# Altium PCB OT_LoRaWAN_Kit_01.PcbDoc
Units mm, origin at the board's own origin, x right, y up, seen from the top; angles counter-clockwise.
Board outline 53.4 x 48.3 mm, 2 copper layers (Top Layer, Bottom Layer); 35 components, 39 nets, 128 pads, 78 vias.
Unrouted connection lines stored in the file: 22.
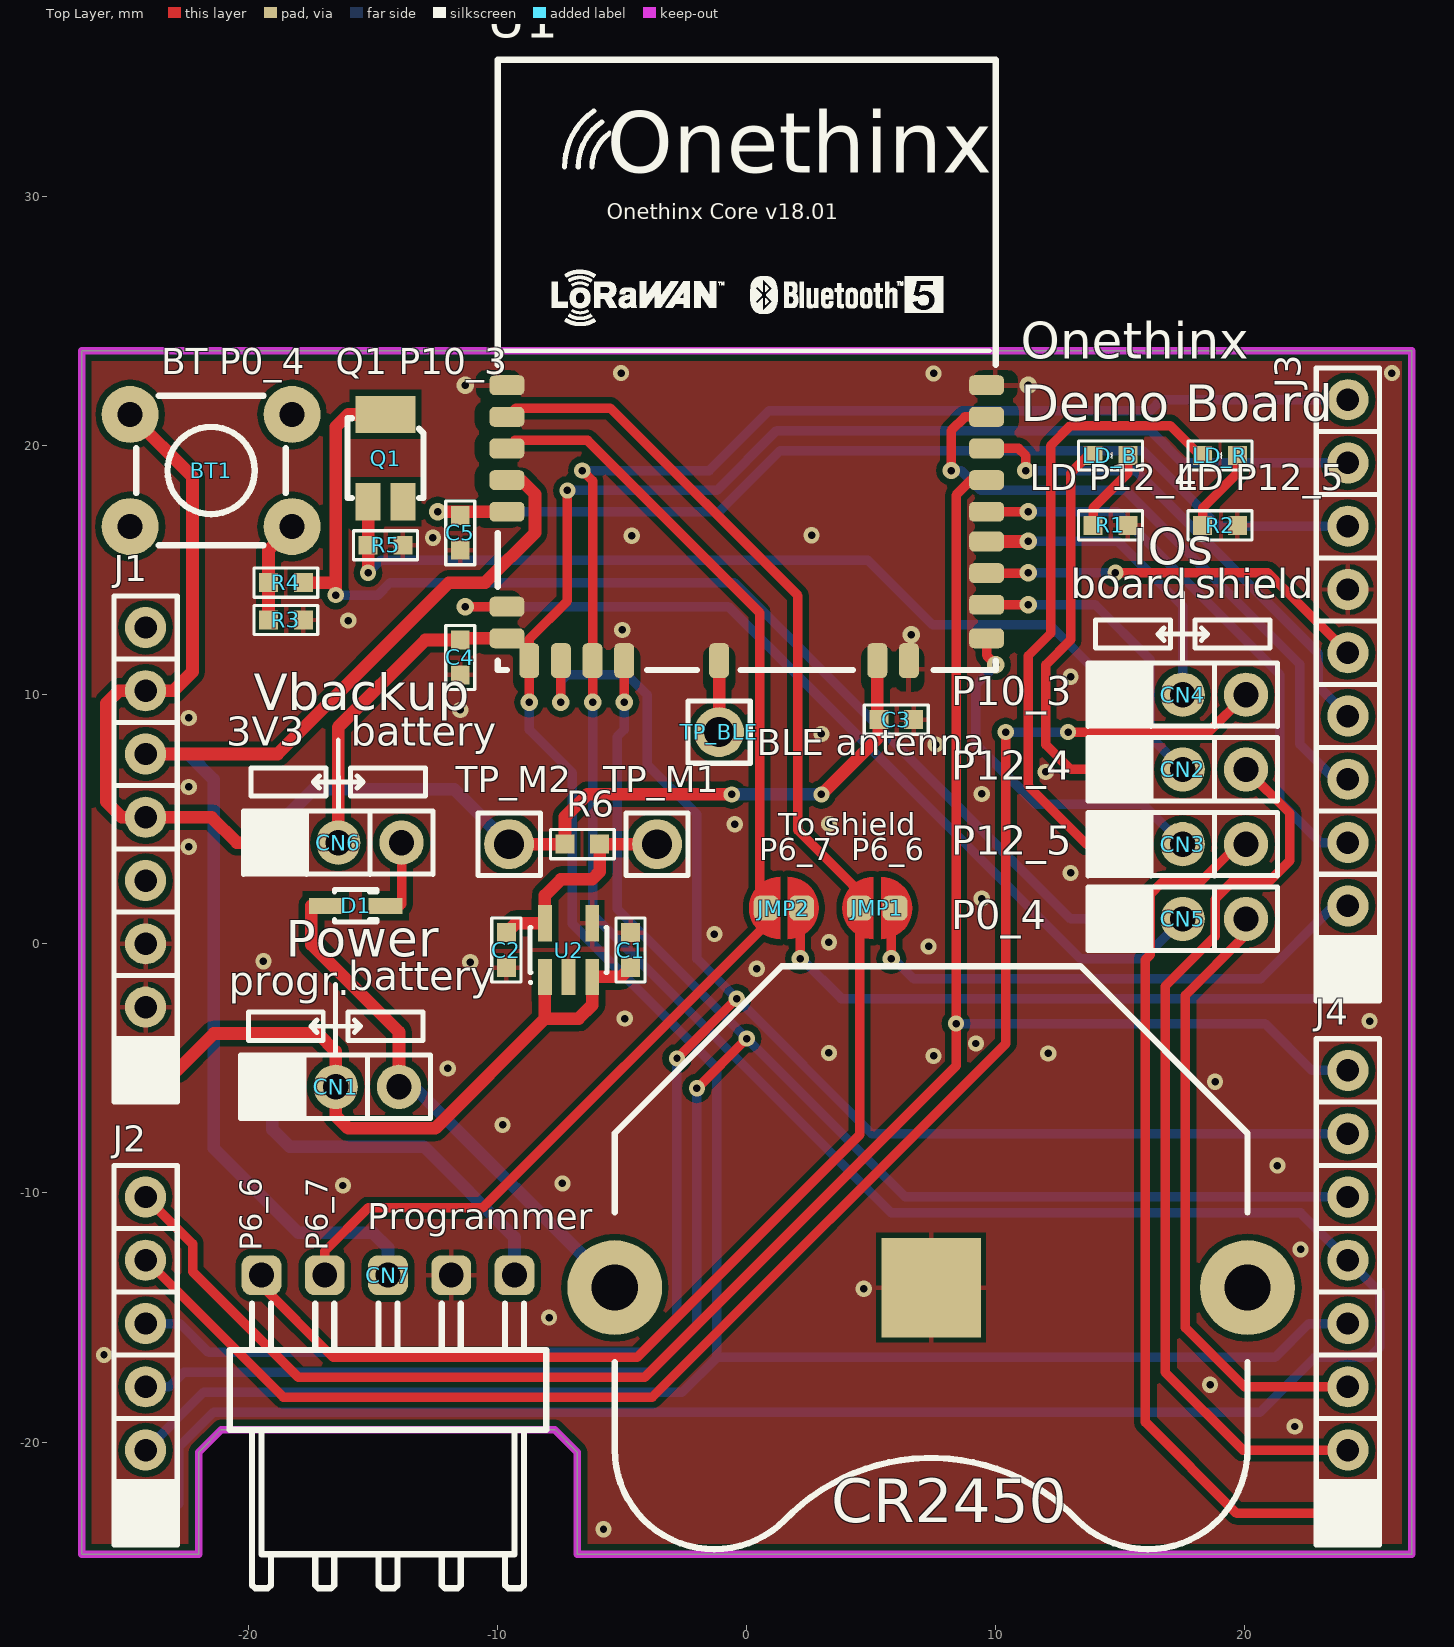
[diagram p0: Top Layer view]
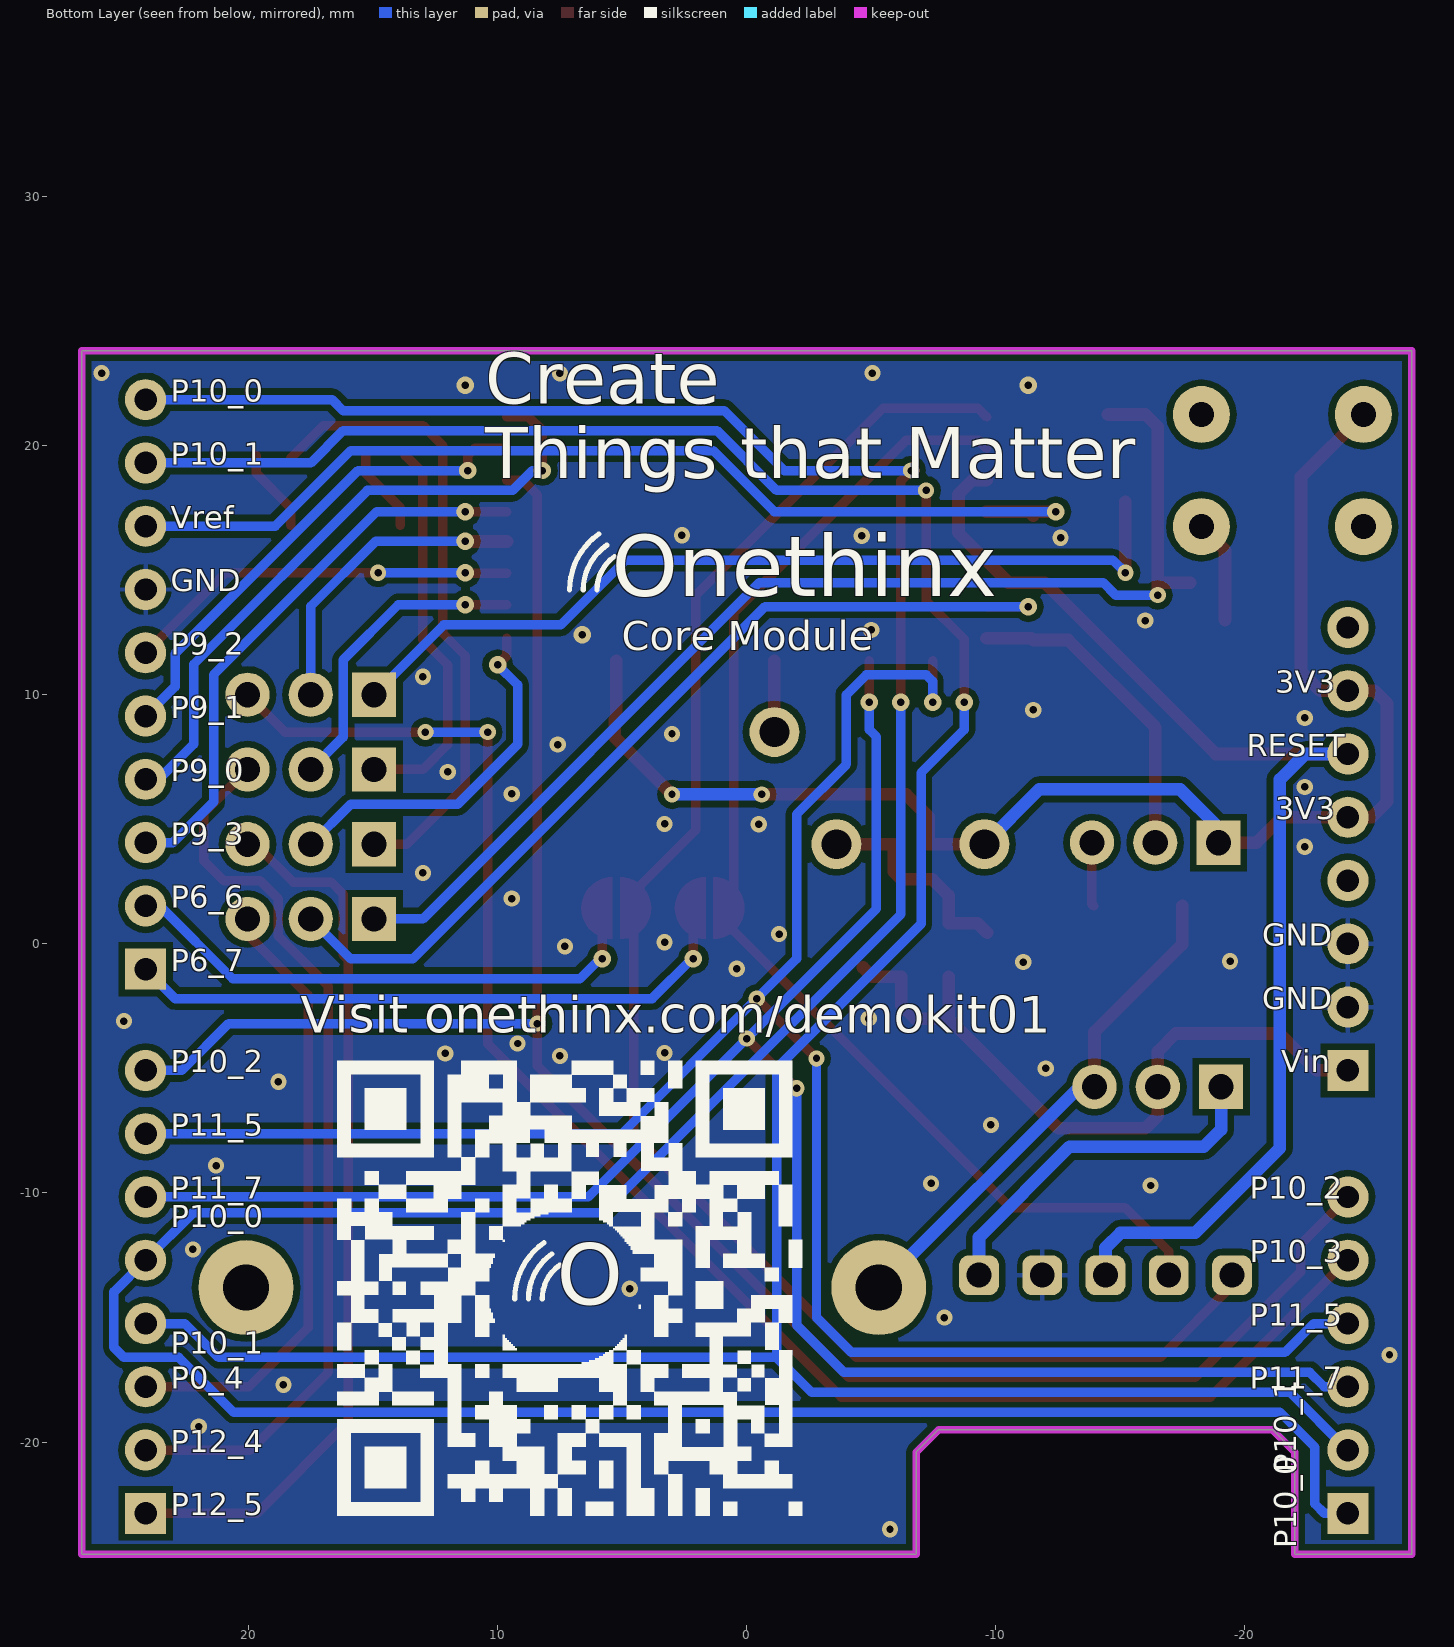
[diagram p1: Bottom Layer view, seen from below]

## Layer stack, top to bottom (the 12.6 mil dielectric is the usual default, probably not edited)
Top Solder: solder mask 0.0102, Solder Resist, Dk 3.5
Top Layer: signal copper 0.0356
Dielectric 1: dielectric 0.32, FR-4, Dk 4.8
Bottom Layer: signal copper 0.0356
Bottom Solder: solder mask 0.0102, Solder Resist, Dk 3.5

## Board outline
-26.7,-24.5 -26.7,23.8 26.7,23.8 26.7,-24.5 -6.8,-24.5 -6.8,-20.4 -7.7,-19.5 -21.1,-19.5 -22,-20.4 -22,-24.5

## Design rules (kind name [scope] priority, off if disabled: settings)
BoardOutlineClearance [All] p1 off: gap=0.25 ignorepadtopadclearanceinfootprint=FALSE except(0: Arc-SplitContinuation Track-SplitContinuation SMDPad-SplitContinuation THPad-SplitContinuation Via-SplitContinuation Fill-SplitContinuation Poly-SplitContinuation Region-SplitContinuation Text-SplitContinuation)
Clearance [IsRegion] p1: gap=0.254 ignorepadtopadclearanceinfootprint=FALSE except(0: Arc-Hole Track-Hole SMDPad-Hole THPad-Hole Via-Hole Fill-Hole Poly-Hole Region-Hole Text-Hole)
Clearance Clearance-xPP-xTP-xTT [All] p2: gap=0.15 ignorepadtopadclearanceinfootprint=FALSE except(0: Arc-Hole Track-Hole SMDPad-Hole THPad-Hole Via-Hole Fill-Hole Poly-Hole Region-Hole Text-Hole)
ComponentClearance [All] p1 off: gap=0.25 collisioncheckmode=3 verticalgap=0.25 showdistances=FALSE
DiffPairsRouting [All] p1: maxlimit=0.25 minlimit=0.25 mostfreqgap=0.25 toplayer_minwidth=0.381 toplayer_maxwidth=0.381 toplayer_prefwidth=0.381 bottomlayer_minwidth=0.381 bottomlayer_maxwidth=0.381 bottomlayer_prefwidth=0.381 maxuncoupledlength=12.5
Height [All] p1: minheight=0 maxheight=25 prefheight=12.5
HoleSize HoleSize-PTH [All] p1: absolutevalues=TRUE maxlimit=2 minlimit=0.25 maxpercent=80.000 minpercent=20.000
HoleToHoleClearance [All] p1: gap=0.35 allowstackedmicrovias=TRUE
MinimumAnnularRing "Minimum IAR  >0.45mm" [((ObjectKind = 'Pad') OR (ObjectKind = 'Via')) And (Layer = 'MultiLayer') And (HoleDiameter > AsMM(0.45))] p1: minimumring=0.175 // minimum inner annular ring for pads > 0.45mm finished hole size
MinimumAnnularRing "Minimum IAR <=0.45mm" [((ObjectKind = 'Pad') OR (ObjectKind = 'Via')) And (Layer = 'MultiLayer') And (HoleDiameter <= AsMM(0.45))] p2: minimumring=0.175 // minimum inner annular ring for pads <= 0.45mm finished hole size
MinimumSolderMaskSliver [All] p1: minsoldermaskwidth=0.08
PlaneClearance PlaneClearance-IPI [All] p1: clearance=0.25
PlaneConnect [All] p1: planeconnectstyle=Relief reliefexpansion=0.175 reliefentries=4 reliefconductorwidth=0.2 reliefairgap=0.2
PolygonConnect [ISVIA OR InComponent('NT1')] p1: connectstyle=Direct reliefconductorwidth=0.254 reliefentries=4 polygonreliefangle="90 Angle" airgapwidth=0.254
PolygonConnect PolygonConnect-xTW [All] p2: connectstyle=Relief reliefconductorwidth=0.2 reliefentries=4 polygonreliefangle="90 Angle" airgapwidth=0.2
RoomDefinition Cy_LoRaWAN_Kit_01 [InComponentClass('Cy_LoRaWAN_Kit_01')] p1: confinementstyle=ConfineOut formatcopy=TRUE lockcomponents=FALSE outline 39,-23 45.5,-23 45.5,-17 39,-17
RoutingCorners [All] p1: cornerstyle=45-Degree minsetback=2.5 maxsetback=2.5
RoutingVias [All] p1: holewidth=0.3 width=0.65 viastyle="Through Hole" minholewidth=0.25 minwidth=0.6 maxholewidth=0.9 maxwidth=1.25
RoutingVias "RoutingVias > 0.45mm" [(ObjectKind = 'Via') And (HoleDiameter > AsMM(0.45))] p2 off: holewidth=0.5 width=0.85 viastyle="Through Hole" minholewidth=0.5 minwidth=0.85 maxholewidth=0.9 maxwidth=1.25 // finishet hole size > 0.45mm
RoutingVias "RoutingVias <= 0.45mm" [(ObjectKind = 'Via') And (HoleDiameter <= AsMM(0.45))] p3 off: holewidth=0.3 width=0.65 viastyle="Through Hole" minholewidth=0.25 minwidth=0.6 maxholewidth=0.45 maxwidth=0.8 // finishet hole size <= 0.45mm
SilkToSilkClearance [All] p1 off: silktosilkclearance=0.2
SilkToSolderMaskClearance SilkscreenOverComponentPads [IsPad] p1 off: minsilkscreentomaskgap=0.2 clearancetoexposedcopper=TRUE
SolderMaskExpansion [All] p1: expansion=0
Width Width-xTW [All] p1: maxlimit=1.5 minlimit=0.15 preferedwidth=0.2
19 further rules are at their usual default settings.

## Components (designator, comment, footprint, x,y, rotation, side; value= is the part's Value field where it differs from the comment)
BT1 "BT P0_4" "BUTTON TACT6x6" -21.5,19 r90 top
C1 "1uF" 0603C-GENERIC -4.665,-0.25 r270 top
C2 "1uF" 0603C-GENERIC -9.652,-0.25 r90 top
C3 "100nF" 0603C-GENERIC 6,9 r180 top
C4 "100nF" 0603C-GENERIC -11.5,11.5 r90 top
C5 "100nF" 0603C-GENERIC -11.5,16.5 r90 top
CN1 "CONNECTOR 1x3" HEADER-1X3 -19.04,-5.734 r90 top
CN2 "CONNECTOR 1x3" HEADER-1X3 14.96,7.006 r90 top
CN3 "CONNECTOR 1x3" HEADER-1X3 14.96,4.006 r90 top
CN4 "CONNECTOR 1x3" HEADER-1X3 14.96,10.006 r90 top
CN5 "CONNECTOR 1x3" HEADER-1X3 14.96,1.006 r90 top
CN6 "CONNECTOR 1x3" HEADER-1X3 -18.937,4.07 r90 top
CN7 "Programmer" "CON Molex 22053051" -14.4,-13.3 r0 top
CR2450 "BAT" "BATT_2450 clip - TH" 7.4,-13.8 r180 top
D1 "BAS16HT1G" SOD323 -15.7,1.524 r0 top
J1 "CONNECTOR 1x8" "SOCKET 2.54 1X8 TH" -24.13,-5.08 r180 top
J2 "CONNECTOR 1x6" "SOCKET 2.54 1X6 TH" -24.13,-22.86 r180 top
J3 "CONNECTOR 1x10" "SOCKET 2.54 1X10 TH" 24.13,-1.016 r180 top
J4 "CONNECTOR 1x8" "SOCKET 2.54 1X8 TH" 24.13,-22.86 r180 top
JMP1 "SWD to shield" "SOLDER JUMPER" 5.24,1.433 r180 top
JMP2 "SWD to shield" "SOLDER JUMPER" 1.489,1.438 r180 top
LD_B "LD P12_4" "LED SMD 0603 (1608)" 14.6,19.6 r180 top
LD_R "LD P12_5" "LED SMD 0603 (1608)" 19,19.6 r180 top
Q1 "Q1 P10_3" PLCC-3_CEB -14.5,19.5 r90 top
R1 "10K" 0603R-GENERIC 14.6,16.8 r180 top
R2 "10K" 0603R-GENERIC 19,16.8 r180 top
R3 "1M" 0603R-GENERIC -18.5,13 r180 top
R4 "1K" 0603R-GENERIC -18.5,14.5 r0 top
R5 "47K" 0603R-GENERIC -14.5,16 r180 top
R6 "0R" 0603R-GENERIC -6.6,4 r0 top
TP_BLE "BLE antenna" "TestPoint 2mm" -1.11,8.5 r0 top
TP_M1 "TestPoint" "TestPoint 2mm" -3.6,4 r90 top
TP_M2 "TestPoint" "TestPoint 2mm" -9.537,4 r90 top
U1 "Onethinx Core V18.01" OnethinxCore_18_01 0,23.495 r0 top
U2 "TPS78330DDC" SOT-23-5 -7.152,-0.25 r0 top

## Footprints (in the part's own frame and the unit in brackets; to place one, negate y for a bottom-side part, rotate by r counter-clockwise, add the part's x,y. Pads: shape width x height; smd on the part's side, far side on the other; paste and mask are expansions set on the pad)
0603C-GENERIC [mil] "CAPACITOR 0603"
  rect 30x30 smd: 1(-27.56,0) 2(27.44,0)
  silkscreen extent -51,-23 50,23, body extent -32,-15 31,15, height 19
0603R-GENERIC [mil] "RESISTOR 0603"
  rect 30x30 smd: 1(-27.5,0) 2(27.5,0)
  silkscreen extent -50,-23 50,23, body extent -32,-15 32,15, height 19
"BATT_2450 clip - TH" [mm] "Battery CR2450 clip"
  rect 4x4 smd: MINUS(0,0)
  round 3.81 hole 1.85: PLUS(-12.7,0) PLUS(12.7,0)
  silkscreen extent -12.7,-12.9 12.7,10.5
"BUTTON TACT6x6" [mm]
  round 2.286 hole 1: 1(-2.25,3.25) 2(2.25,3.25) 3(-2.25,-3.25) 4(2.25,-3.25)
  silkscreen extent -3,-3 3,3, body extent -3,-3.85 3,3.85, height 9.5
"CON Molex 22053051" [mm] "5 way 2.54mm RA TH"
  rrect50% 1.6x1.6 hole 1: 1(-5.08,0) 2(-2.54,0) 3(0,0) 4(2.54,0) 5(5.08,0)
  silkscreen extent -6.35,-12.57 6.35,-1.14
HEADER-1X3 [mil]
  rect 70x70 hole 40: 1(-0.25,0)
  round 70 hole 40: 2(-0.25,-100) 3(-0.25,-200)
  silkscreen extent -50,-250 50,50, body extent -50,-250 50,50, height 354
"LED SMD 0603 (1608)" [mil] "LED 0603"
  rect 30x30 smd: A(27.5,0) K(-27.5,0)
  silkscreen extent -50,-23 50,23, body extent -30,-15 30,15, height 43
OnethinxCore_18_01 [mm] "Onethinx LoRaWAN Core V18.01"
  rrect50% 1.4x0.8 smd: 1(-9.625,-1.07) 2(-9.625,-2.34) 3(-9.625,-3.61) 4(-9.625,-4.88) 5(-9.625,-6.15) 6(-9.625,-9.96) 7(-9.625,-11.23) 15(9.625,-11.23) 16(9.625,-9.882) 17(9.625,-8.612) 18(9.625,-7.342) 19(9.625,-6.15) 20(9.625,-4.88) 21(9.625,-3.61) 22(9.625,-2.34) 23(9.625,-1.07)
  rrect50% 0.8x1.4 smd: 8(-8.73,-12.125) 9(-7.46,-12.125) 10(-6.19,-12.125) 11(-4.92,-12.125) 12(-1.11,-12.125) 13(5.24,-12.125) 14(6.51,-12.125)
  silkscreen extent -10,-12.5 10,12, body extent -8.5,-11 8.5,10.54, height 1.7
PLCC-3_CEB [mm]
  rect 1.5x1 smd: B(-1.75,-0.7) E(-1.75,0.7)
  rect 1.5x2.4 smd: C(1.75,0)
  silkscreen extent -1.6,-1.53 1.6,1.53, body extent -1.75,-1.4 1.75,1.4, height 1.95
"SOCKET 2.54 1X6 TH" [mil] "SOCKET 2.54 1X6 TH"
  rect 65x65 hole 35.43: 1(0,0)
  round 65 hole 35.43: 2(0,-100) 3(0,-200) 4(0,-300) 5(0,-400) 6(0,-500)
  silkscreen extent -50,-550 50,50, body extent -50,-550 50,50, height 295
"SOCKET 2.54 1X8 TH" [mil] "SOCKET 2.54 1X8 TH"
  rect 65x65 hole 35.43: 1(0,0)
  round 65 hole 35.43: 2(0,-100) 3(0,-200) 4(0,-300) 5(0,-400) 6(0,-500) 7(0,-600) 8(0,-700)
  silkscreen extent -50,-750 50,50, body extent -50,-750 50,50, height 295
"SOCKET 2.54 1X10 TH" [mil] "SOCKET 2.54 1X10 TH"
  rect 65x65 hole 35.43: 1(0,0)
  round 65 hole 35.43: 2(0,-100) 3(0,-200) 4(0,-300) 5(0,-400) 6(0,-500) 7(0,-600) 8(0,-700) 9(0,-800) 10(0,-900)
  silkscreen extent -50,-950 50,50, body extent -50,-950 50,50, height 295
SOD323 [mm]
  rect 1.35x0.65 smd: A(-1.2,0) K(1.2,0)
  silkscreen extent -0.85,-0.65 0.85,0.65, body extent -1.25,-0.63 1.25,0.63, height 0.9
"SOLDER JUMPER" [mm] "Solder Jumper 2mm"
  rrect50% 1x1 smd paste-10 mask+0: A(-0.711,0) B(0.711,0)
  Top Layer region: -0.152,1.25 -0.152,-1.25 -0.629,-1.155 -1.032,-0.885 -1.302,-0.482 -1.397,-0.005 -1.397,-0.005 -1.397,0.005 -1.302,0.482 -1.032,0.885 -0.629,1.155 -0.152,1.25
  Top Layer region: 0.152,-1.25 0.152,1.25 0.629,1.155 1.032,0.885 1.302,0.482 1.397,0.005 1.397,0.005 1.397,-0.005 1.302,-0.482 1.032,-0.885 0.629,-1.155 0.152,-1.25
SOT-23-5 [mm]
  rect 0.55x1.45 smd: 1(-0.95,-1.075) 2(0,-1.075) 3(0.95,-1.075) 4(0.95,1.075) 5(-0.95,1.075)
  silkscreen extent -1.57,-1.35 1.55,0.9, body extent -1.45,-1.4 1.45,1.4, height 1.09
"TestPoint 2mm" [mm] "Test Point 2mm"
  round 2 hole 1.2: 1(0,0)
  silkscreen extent -1.25,-1.25 1.25,1.25

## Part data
BT1: library part SW-TACT, "FSM4JH"
C1 C2 C3 C4 C5: library part CAP, "Capacitor"
CN1 CN2 CN3 CN4 CN5 CN6: "Harwin M20-9990345"
CN7: library part "CONNECTOR 1x5", "CON Molex 22053051"
CR2450: "Battery"
D1: library part Diode, "Diode"
JMP1: library part SolderJumper
JMP2: library part SolderJumper, "Solder Jumper"
LD_B: library part LED, "Wurth 150060BS73220"
LD_R: library part LED, "Wurth 150060RS75000"
Q1: library part Phototransistor, "Phototransistor Vishay VEMT4700-GS08"
R1 R2 R3 R4 R5 R6: library part RES, "Resistor"
TP_BLE: library part TestPoint, "Test Point"
TP_M1 TP_M2: "Test Point"
U1: library part Onethinx_Core_18_01, "PSoC Mixed Signal Array"
U2: library part "Voltage Regulator_EN_ADJ"

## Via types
v1: diameter 0.65, hole 0.3, Top Layer to Bottom Layer, tented both sides, 60 vias
v2: diameter 0.7, hole 0.3, Top Layer to Bottom Layer, tented both sides, 18 vias

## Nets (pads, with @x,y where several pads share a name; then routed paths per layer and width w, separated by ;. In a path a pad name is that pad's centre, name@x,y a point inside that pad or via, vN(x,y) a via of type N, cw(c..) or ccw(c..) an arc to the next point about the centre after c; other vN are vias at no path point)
3V3: BT1.2 BT1.4 C3.2 CN6.1 J1.5 J1.7 R6.1 TP_M2.1 U1.13 | length 58.6
  Top Layer w0.508: BT1.2 -22.25,18.75 -22.25,10.924 -23.014,10.16 J1.7 -25.2,10.16 -25.7,9.66 -25.7,5.7 -25.08,5.08 J1.5 -21.48,5.08 -20.464,4.064 CN6.1 ; TP_M2.1 R6.1 -7.299,5.101 -6.4,6 v1(-0.6,6) ; v1(3,6) 5.303,8.303 C3.2 5.24,9.063 U1.13
  Bottom Layer w0.508: CN6.1 -18.937,4.663 -17.4,6.2 -11.737,6.2 TP_M2.1 ; v1(-0.6,6) v1(3,6)
"BUTTON / L_POWER": CN5.1 Q1.C R4.2 | length 47.5
  Top Layer w0.508: R4.2 -16.5,14.5 ; v1(-16.5,14) -16.5,14.5 ; Q1.C -16,21.25 -16.5,20.75 -16.5,14.5
  Bottom Layer w0.381: v1(-16.5,14) -14.808,14 -14.308,14.5 -0.5,14.5 13,1 CN5.1
GND: C1.1 C2.1 C3.1 C4.1 C5.1 CN7.4 CR2450.MINUS J1.2 J1.3 J3.7 R1.1 R2.1 R3.1 R5.1 U1.1 U1.14 U1.23 U2.2 U2.4
  other v1: -5.75,-23.5 22,-19.373 18.6,-17.7 -25.8,-16.5 -7.934,-15 4.699,-13.843 22.23,-12.266 -16.21,-9.7 -7.4,-9.616 21.3,-8.9 -9.8,-7.266 18.8,-5.533 -12,-5 7.5,-4.5 12.1,-4.4 3.3,-4.378 9.2,-4 25,-3.1 -4.9,-3 0.4,-1 -11.1,-0.731 -19.4,-0.7 7.3,-0.104 3.3,0.064 -1.3,0.393 9.431,1.815 13,2.847 -22.4,3.9 -0.482,4.8 3.3,4.815 9.431,6.019 -22.4,6.3 12,6.9 7.584,8 3,8.427 -22.4,9.071 -11.5,9.39 13,10.72 -5,12.6 -16,12.976 -12.6,16.3 -4.62,16.385 2.6,16.4 7.5,22.896 -5.043,22.913 25.9,22.913
  other v2: 6.6,12.4 -11.3,22.425 11.3,22.425
LED_B: CN2.1 LD_B.A | length 15.7
  Top Layer w0.381: LD_B.A@13.701,19.6 13,18.898 13,12.2 12,11.2 12,8 13,7 CN2.1
LED_R: CN3.1 LD_R.A | length 25.6
  Top Layer w0.381: CN3.1 13.64,4 11.3,6.34 11.3,11.565 12.2,12.465 12.2,20 13,20.8 17.002,20.8 LD_R.A@18.302,19.5
LIGHT: CN4.1 Q1.E R5.2 | length 35.5
  Top Layer w0.508: v1(-15.2,14.9) -15.198,14.902 R5.2 -15.2,16.002 Q1.E
  Bottom Layer w0.381: v1(-15.2,14.9) -14.7,15.4 4.865,15.4 7.465,12.8 12.16,12.8 CN4.1
NetBT1_1: BT1.1 BT1.3 R3.2 R4.1 | length 4.1
  Top Layer w0.508: R3.2 R4.1 -19.199,15.801 BT1.3
NetC2_2: C2.2 R6.2 TP_M1.1 U2.5 | length 8.8
  Top Layer w0.508: C2.2 -9.274,0.825 U2.5 -8.102,1.945 -7.458,2.588 -6.212,2.588 -5.902,2.898 R6.2 TP_M1.1
NetCN6_3: CN6.3 D1.K | length 2.6
  Top Layer w0.381: D1.K@-13.925,1.524 -13.857,1.592 CN6.3
NetJ3_1: J3.1 JMP2.A | length 25.1
  Top Layer w0.381: v2(2.143,-0.6) 2.143,0.283 2.143,1.381 JMP2.A
  Bottom Layer w0.381: v2@2.2,-0.6 3.8,-2.2 22.946,-2.2 J3.1
NetJ3_2: J3.2 JMP1.A | length 21.9
  Top Layer w0.381: v2(5.8,-0.6) 5.8,0.243 5.8,1.282 JMP1.A
  Bottom Layer w0.381: v2@5.894,-0.6 6.694,-1.4 20.63,-1.4 23.554,1.524 J3.2
NetLD_B_K: LD_B.K R1.2 | length 3.4
  Top Layer w0.381: R1.2 13.901,17.501 15.298,18.898 LD_B.K
NetLD_R_K: LD_R.K R2.2 | length 3.4
  Top Layer w0.381: R2.2 18.302,17.502 19.699,18.899 LD_R.K
NetTP_BLE_1: TP_BLE.1 U1.12 | length 2.9
  Top Layer w0.508: TP_BLE.1 U1.12
P9_0: J3.4 U1.22 | length 26.2
  Top Layer w0.381: v2(8.2,19) 8.2,20.6 8.755,21.155 U1.22
  Bottom Layer w0.381: v2(8.2,19) 8.6,19 9.4,18.2 15.224,18.2 22.2,11.224 22.2,8.02 23.616,6.604 J3.4
P9_1: J3.5 U1.21 | length 20.1
  Top Layer w0.381: U1.21 10.915,19.885 11.2,19.6 v2(11.2,19)
  Bottom Layer w0.381: v2(11.2,19) 15.6,19 22.946,11.654 22.946,10.328 J3.5
P9_2: J3.6 U1.17 | length 15.8
  Top Layer w0.381: U1.17 11.282,14.883 v2(11.3,14.9) ; v1(14.8,14.9) 20.914,14.9 J3.6
  Bottom Layer w0.381: v2(11.3,14.9) v1(14.8,14.9)
P9_3: J3.3 U1.19 | length 23
  Top Layer w0.381: U1.19 v2(11.3,17.345)
  Bottom Layer w0.381: v2(11.3,17.345) 14.855,17.345 21.4,10.8 21.4,5.7 23.036,4.064 J3.3
P10_0: J2.1 J3.10 J4.5 U1.10 | length 143.6
  Top Layer w0.381: v1(-6.6,19) -6.19,18.59 U1.10 v2(-6.19,9.7)
  Bottom Layer w0.381: J2.1 -23.187,-22.86 -22.8,-22.473 -22.8,-20.2 -21.4,-18.8 20.6,-18.8 22.8,-16.6 25,-16.6 25.4,-16.2 25.4,-13.97 J4.5 22.23,-10.8 5.8,-10.8 -6.19,1.19 v2(-6.19,9.7) ; v1(-6.6,19) -1.504,19 0.896,21.4 16.2,21.4 16.644,21.844 J3.10
P10_1: J2.2 J3.9 J4.4 U1.8 | length 121.8
  Top Layer w0.381: v2(-8.73,9.7) U1.8 -8.73,12.235 -7.2,13.765 v1(-7.2,18.2)
  Bottom Layer w0.381: J2.2 -24.12,-20.32 -21.8,-18 -2.6,-18 -1.2,-16.6 ; v2(-8.73,9.7) -8.73,8.6 -7,6.87 -7,0.8 -1.2,-5 -1.2,-16.6 ; v1(-7.2,18.2) -1.2,18.2 1.2,20.6 16.2,20.6 17.496,19.304 J3.9 ; J4.4 22.56,-15.24 21.2,-16.6 -1.2,-16.6
P10_2: J2.6 J4.8 U1.20 | length 82.3
  Top Layer w0.381: J2.6 -22.245,-12.045 -22.245,-13.155 -18,-17.4 -4.1,-17.4 8.4,-4.9 v1(8.4,-3.2) 8.4,18.015 9,18.615 U1.20
  Bottom Layer w0.381: v1(8.4,-3.2) 20.8,-3.2 22.68,-5.08 J4.8
P10_3: CN4.2 U1.18 | length 12.5
  Top Layer w0.508: U1.18 v2(11.3,16.153)
  Bottom Layer w0.381: v2(11.3,16.153) 14.9,16.153 17.5,13.553 CN4.2
P11_5: J2.4 J4.7 U1.9 | length 83.1
  Top Layer w0.381: v2(-7.46,9.7) U1.9 ; v1(-2.8,-4.6) v1(-0.4,-2.2)
  Bottom Layer w0.381: J2.4 -22.76,-15.24 -21.6,-16.4 -4.2,-16.4 -2.8,-15 v1(-2.8,-4.6) ; v2(-7.46,9.7) -7.46,10.54 -7.2,10.8 -4.8,10.8 -4,10 -4,7.2 -2,5.2 -2,-0.6 v1(-0.4,-2.2) 5.02,-7.62 J4.7
P11_7: J2.3 J4.6 U1.11 | length 79.7
  Top Layer w0.381: v2(-4.92,9.7) U1.11 ; v1(-2,-5.8) v1(0,-3.8)
  Bottom Layer w0.381: J2.3 -23.18,-17.78 -22.6,-17.2 -3.9,-17.2 -2,-15.3 v1(-2,-5.8) ; v2(-4.92,9.7) -4.92,8.6 -5.2,8.32 -5.2,1.4 v1(0,-3.8) 6.36,-10.16 J4.6
P12_4: CN2.2 U1.16 | length 12.4
  Top Layer w0.381: U1.16 v2(11.3,13.613)
  Bottom Layer w0.381: v2(11.3,13.613) 13.988,13.613 16.2,11.4 16.2,8.3 CN2.2
P12_5: CN3.2 U1.15 | length 14.7
  Top Layer w0.381: U1.15 9.625,11.575 v2(10,11.2)
  Bottom Layer w0.381: v2(10,11.2) 9.2,10.4 9.2,8.004 11.604,5.6 15.9,5.6 CN3.2
SH_P10_3: CN4.3 J2.5 | length 65.6
  Top Layer w0.381: J2.5 -24.1,-12.7 -18.6,-18.2 -3.8,-18.2 10.4,-4 v1(10.4,8.5) ; v1@12.8,8.5 v1(12.9,8.5) 18.54,8.5 CN4.3
  Bottom Layer w0.381: v1(10.4,8.5) v1(12.9,8.5)
SH_P12_4: CN2.3 J4.2 | length 36.5
  Top Layer w0.381: CN2.3 21.8,5.24 21.8,3.34 21,2.54 19.54,2.54 18.8,1.8 18.8,0.305 16.8,-1.695 16.8,-17.2 19.92,-20.32 J4.2
SH_P12_5: CN3.3 J4.1 | length 35.6
  Top Layer w0.381: CN3.3 19.728,4 18.2,2.472 16.675,2.472 16.2,1.997 16.2,-0.433 16,-0.633 16,-19.2 19.66,-22.86 J4.1
SH_WU_P0_4: CN5.3 J4.3 | length 24.9
  Top Layer w0.381: CN5.3 20.04,0.373 17.6,-2.067 17.6,-15.4 19.98,-17.78 J4.3
SWD_CLK_P6_7: CN7.2 JMP2.B U1.3 | length 49.9
  Top Layer w0.381: CN7.2 -16.94,-12.34 -15.2,-10.6 -10.6,-10.6 0.822,0.822 0.929,1.106 JMP2.B 0.518,1.698 0.518,13.3 -6.388,20.205 -9.305,20.205 U1.3
SWD_IO_P6_6: CN7.1 JMP1.B U1.2 | length 67
  Top Layer w0.381: CN7.1 -19.48,-13.72 -16.6,-16.6 -4.4,-16.6 4.529,-7.671 4.529,0.303 JMP1.B JMP1.B@4.529,1.527 ; U1.2 -9.28,21.5 -5.47,21.5 2.053,13.977 2.053,4.56 4.239,2.374 4.529,2.084 JMP1.B@4.529,1.527 ; JMP1.B@4.6,1.524 4.532,1.524 JMP1.B@4.529,1.527
Vbackup: C4.2 CN6.2 U1.7 | length 12.9
  Top Layer w0.508: CN6.2 -16.397,8.701 -12.902,12.197 C4.2 -11.432,12.265 U1.7
Vbatt: CN1.3 CR2450.PLUS D1.A | length 20.7
  Top Layer w0.508: D1.A@-17.475,1.524 -17.475,-0.025 -13.96,-3.54 CN1.3
  Bottom Layer w0.508: CN1.3 -13.36,-5.74 CR2450.PLUS@-5.3,-13.8
Vin: C1.2 CN1.2 J1.1 U2.1 U2.3 | length 28.2
  Top Layer w0.508: J1.1 -22.872,-5.08 -21.392,-3.6 -17.217,-3.6 -16.5,-4.317 CN1.2 -16.5,-6.9 -16,-7.4 -12.502,-7.4 -8.102,-3 ; U2.1 -8.102,-3 ; C1.2 -5.043,-1.325 U2.3 -6.202,-2.452 -6.75,-3 -8.102,-3
Vprog: CN1.1 CN7.5 | length 14.7
  Bottom Layer w0.508: CN1.1 -19.04,-7.45 -18.35,-8.14 -12.96,-8.14 -9.32,-11.78 CN7.5
Vref: C5.2 J3.8 U1.5 | length 42.8
  Top Layer w0.508: C5.2 -11.352,17.345 v2(-12.4,17.345) U1.5
  Bottom Layer w0.381: v2(-12.4,17.345) -1.11,17.345 1.345,19.8 15.898,19.8 18.934,16.764 J3.8
WAKEUP_P0_4: CN5.2 U1.6 | length 37
  Top Layer w0.381: v2(-11.3,13.535) U1.6
  Bottom Layer w0.381: v2(-11.3,13.535) -0.735,13.535 13.4,-0.6 15.9,-0.6 CN5.2
XRES: CN7.3 J1.6 U1.4 | length 49.9
  Top Layer w0.508: J1.6 -18.83,7.62 -11.95,14.5 -10.5,14.5 -8.5,16.5 -8.5,18.05 -9.065,18.615 U1.4
  Bottom Layer w0.508: J1.6 -22.42,7.62 -21.4,6.6 -21.4,-8.2 -18,-11.6 -15,-11.6 -14.4,-12.2 CN7.3
pads on no net: J1.4 J1.8 Q1.B

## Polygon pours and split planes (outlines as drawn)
GND on Top Layer "Top Layer-GND" (solid, pour order 0): -26.4,23.5 -26.4,-24.2 -21.4,-24.2 -21.4,-19.2 -7.4,-19.2 -7.4,-24.2 26.4,-24.2 26.4,23.5
no net on Top Layer "Top Layer-No Net" (solid, pour order 2): -12.7,22
GND on Bottom Layer "Bottom Layer-GND" (solid, pour order 4): -26.4,23.5 -26.4,-24.2 -21.4,-24.2 -21.4,-19.2 -7.4,-19.2 -7.4,-24.2 26.4,-24.2 26.4,23.5

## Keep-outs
Keep-Out Layer:
  the board outline again, w0.3

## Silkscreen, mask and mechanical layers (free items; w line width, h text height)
Top Overlay:
  lines w0.2: -17.501,-3.308 -17.251,-3.058 ; -17.397,6.497 -15.397,6.497 ; -17.251,-3.557 -17.501,-3.307 -15.5,-3.307 ; -17.148,6.247 -17.398,6.497 -17.148,6.746 ; -16.5,-4.464 -16.5,-1.627 ; -16.397,5.34 -16.397,8.177 ; -15.75,-3.556 -15.5,-3.306 -15.5,-3.307 ; -15.751,-3.057 -15.501,-3.307 ; -15.648,6.747 -15.398,6.497 ; -15.647,6.248 -15.397,6.498 -15.397,6.497 ; 16.749,12.182 16.499,12.432 ; 16.749,12.682 16.499,12.432 ; 17.5,14.112 17.5,11.276 ; 18.249,12.682 18.499,12.432 ; 18.25,12.184 18.5,12.434 18.5,12.432 16.5,12.432 ; -20,-3.87 -17,-3.87 -17,-2.74 -20,-2.74 -20,-3.87 ; -19.897,5.934 -16.897,5.934 -16.897,7.064 -19.897,7.064 -19.897,5.934 ; -16,-3.87 -13,-3.87 -13,-2.74 -16,-2.74 -16,-3.87 ; -15.897,5.934 -12.897,5.934 -12.897,7.064 -15.897,7.064 -15.897,5.934 ; 14,11.87 14,13 17,13 17,11.87 14,11.87 ; 18,11.87 18,13 21,13 21,11.87 18,11.87
  text "Onethinx / Demo Board" at 11,20.5 h2.5
  text "IOs" at 15.5,14.745 h2.5
  text "board" at 13,13.5 h2
  text "shield" at 18,13.5 h2
  text "P10_3" at 8.2,9.2 h2
  text "Vbackup" at -19.783,8.89 h2.5
  text "3V3" at -20.897,7.564 h2
  text "battery" at -15.897,7.564 h2
  text "P12_4" at 8.2,6.2 h2
  text "To shield" at 1.27,4.064 h1.52
  text "P12_5" at 8.2,3.2 h2
  text "P6_7" at 0.508,3.048 h1.52
  text "P6_6" at 4.191,3.048 h1.52
  text "P0_4" at 8.2,0.2 h2
  text "Power" at -18.5,-0.995 h2.5
  text "battery" at -16,-2.24 h2
  text "progr." at -20.8,-2.44 h2
  text "P6_6" at -19.177,-12.319 h1.52 r90
  text "P6_7" at -16.51,-12.319 h1.52 r90
Bottom Overlay:
  drawing of 40 lines, arcs and shapes, not listed
  text "P10_0" at 23.114,21.463 h1.52
  text "Create" at 10.5,21 h3.5
  text "P10_1" at 23.114,18.923 h1.52
  text "Things that Matter" at 10.5,18 h3.5
  text "Vref" at 23.114,16.383 h1.52
  text "GND" at 23.114,13.843 h1.52
  text "Onethinx" at 5.424,13.137 h4.25
  text "Core Module" at 5.02,11.402 h2
  text "P9_2" at 23.114,11.303 h1.52
  text "3V3" at -21.209,9.779 h1.52
  text "P9_1" at 23.114,8.763 h1.52
  text "RESET" at -20.066,7.239 h1.52
  text "P9_0" at 23.114,6.223 h1.52
  text "3V3" at -21.209,4.699 h1.52
  text "P9_3" at 23.114,3.683 h1.52
  text "P6_6" at 23.114,1.143 h1.52
  text "GND" at -20.701,-0.381 h1.52
  text "P6_7" at 23.114,-1.397 h1.52
  text "GND" at -20.701,-2.921 h1.52
  text "Visit onethinx.com/demokit01" at 17.9,-4.05 h2.5
  text "Vin" at -21.463,-5.461 h1.52
  text "P10_2" at 23.114,-5.461 h1.52
  text "P11_5" at 23.114,-8.001 h1.52
  text "P10_2" at -20.193,-10.541 h1.52
  text "P11_7" at 23.114,-10.541 h1.52
  text "P10_0" at 23.114,-11.684 h1.52
  text "P10_3" at -20.193,-13.081 h1.52
  text "O" at 7.625,-15.312 h4.25
  text "P11_5" at -20.193,-15.621 h1.52
  text "P10_1" at 23.114,-16.764 h1.52
  text "P11_7" at -20.193,-18.161 h1.52
  text "P0_4" at 23.114,-18.161 h1.52
  text "P12_4" at 23.114,-20.701 h1.52
  text "P10_1" at -22.352,-21.209 h1.52 r270
  text "P12_5" at 23.114,-23.241 h1.52
  text "P10_0" at -22.352,-24.257 h1.52 r270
